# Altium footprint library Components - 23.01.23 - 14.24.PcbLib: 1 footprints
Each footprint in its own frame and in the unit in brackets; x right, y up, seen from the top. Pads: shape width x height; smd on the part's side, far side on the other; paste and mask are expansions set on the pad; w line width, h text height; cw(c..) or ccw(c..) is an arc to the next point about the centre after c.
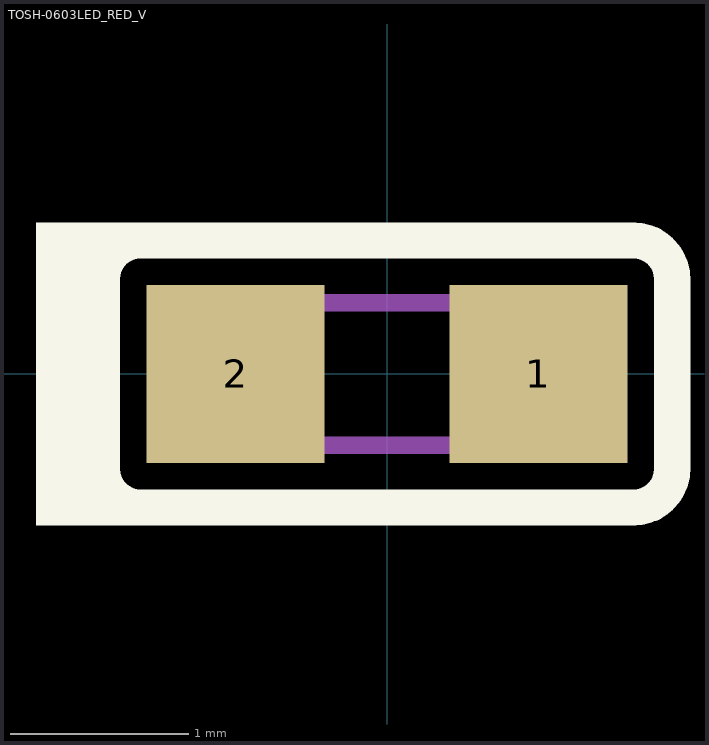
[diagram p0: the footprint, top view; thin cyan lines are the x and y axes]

## TOSH-0603LED_RED_V [mm] "SMT LED, 2-Leads, Body 1.6x0.8mm (0603-Size)"
pads (2):
  rect 1x1 smd paste+0 mask+0: 1(0.85,0) 2(-0.85,0)
Top Overlay:
  rectangle: -1.782,-0.851 -1.198,-0.686
  rectangle: -1.973,-0.851 -1.516,0.851
  rectangle: -1.782,0.665 -1.132,0.851
  lines w0.203: -1.602,-0.533 ccw(c-1.386,-0.533) -1.386,-0.749 1.386,-0.749 ccw(c1.386,-0.533) 1.602,-0.533 1.602,0.533 ccw(c1.386,0.533) 1.386,0.749 -1.386,0.749 ccw(c-1.386,0.533) -1.602,0.533 -1.602,-0.533
Mechanical 7:
  lines w0.1: -0.8,-0.4 0.8,-0.4 0.8,0.4 -0.8,0.4 -0.8,-0.4
  text ".Designator" at -1.6,0.6 h0.4
  text ".Comment" at -1.6,-0.9 h0.4
3D body: height 0.38, standoff 0, extent 0.664,-0.532 1.089,0.532
3D body: height 0.38, standoff 0, extent -0.925,-0.535 -0.5,0.535
3D body: height 0.38, standoff 0, extent -0.502,-0.533 0.668,0.533
3D body: height 0.6, standoff 0, extent -0.301,-0.464 0.493,0.402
